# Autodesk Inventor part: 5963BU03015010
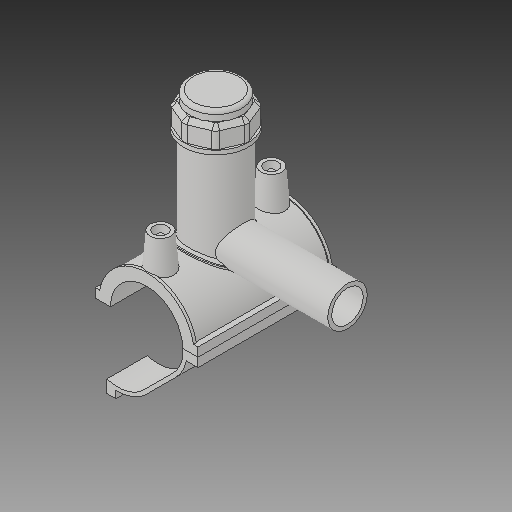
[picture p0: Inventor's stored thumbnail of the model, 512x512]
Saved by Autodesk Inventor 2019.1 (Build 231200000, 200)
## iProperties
Created: 2017-07
Part Number: 5963BU03015010
Material: Generic
Description: PLASSON TAPPING SADDLE 1 1/2''IPS x 1''CTS
Document SubType Name: Modeling
Designer: KIM
Mass: 1712.7 g
Surface Area: 2671.49 cm^2
Volume: 1712.7 cm^3
Density: 1 g/cm^3
Appearance: Default
Author: KIM
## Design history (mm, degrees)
derived "5963B.ipt"
feature "Solid1::5963B.ipt"
feature "Solid2::5963B.ipt"
feature "Solid4::5963B.ipt"
feature "Solid5::5963B.ipt"
tag "TaggingFeature1"
body "Solid1"
body "Solid2"
other parameters: "d0" = 52.1, "d2" = 74.168, "d3" = 13.025, "d4" = 100.076, "d5" = 0, "d6" = 0.1, "d8" = 0, "d19" = 6, "d20" = 6, "d21" = 60.0456, "d23" = 0, "d24" = 30.0228, "d26" = 0, "d29" = 3, "d30" = 17.36667, "d31" = 6, "d32" = 0, "d33" = 0, "d34" = 0.6, "d40" = 35.2196, "d41" = 46.89, "d43" = 0, "d45" = 0, "d47" = 93.9106, "d70" = 15, "d72" = 0, "d73" = 6, "d75" = 5, "d76" = 0, "d77" = 2.605, "d78" = 56.05, "d79" = 15, "d80" = 40.0304, "d82" = 5 deg, "d84" = 4, "d85" = 14, "d86" = 0, "d87" = 3, "d88" = 0, "d89" = 1, "d90" = 1, "d91" = 80.0608, "d92" = 0, "d93" = 0.5, "d94" = 27.42105, "d96" = 69.0846, "d97" = 2.00152, "d98" = 0, "d102" = 0.521, "d120" = 140 deg, "d121" = 24.228, "d122" = 20 deg, "d123" = 135.46, "d124" = 40.638, "d126" = 0, "d143" = 53.663, "d145" = 12.02308, "d149" = 0.7815, "d150" = 13.22538, "d153" = 100.076, "d154" = 0, "d156" = 33.865, "d157" = 160 deg, "d159" = 3.126, "d161" = 0.7815, "d162" = 60.0456, "d163" = 0, "d164" = 26.05, "d167" = 5.21, "d168" = 33.03902, "d170" = 3.2805, "d172" = 0, "d173" = 1, "d175" = 26.05, "d176" = 20 deg, "d177" = 3.647, "d178" = 15.63, "d180" = 0, "d183" = 6.252, "d184" = 2.9176, "d185" = 32.5247, "d186" = 32.5247, "d187" = 33.865, "d188" = 4.689, "d189" = 3.647, "d190" = 0, "d191" = 50.7975, "d193" = 6.1236, "d194" = 3.50266, "d195" = 90 deg, "d197" = 0, "d199" = 0, "d200" = 7.815, "d202" = 0, "d203" = 98.044, "d204" = 44.5455, "d205" = 32.823, "d206" = 39.8565, "d207" = 73.533, "d208" = 76.47432, "d209" = 91.18092, "d210" = 40.3254, "d211" = 46.89, "d212" = 37.512, "d213" = -3.8871, "d216" = 0, "d217" = 5.21, "d218" = 2.605, "d219" = 0.521, "d222" = 52.1, "d224" = 0, "d230" = 3.126, "d233" = 6, "d236" = 37.084, "d237" = 30.0228, "d238" = 6.02433, "d240" = 30.0228, "d241" = 30.0228, "d242" = 30.0228, "d243" = 6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
